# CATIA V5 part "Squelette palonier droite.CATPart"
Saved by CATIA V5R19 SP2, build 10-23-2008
Part number: Squelette palonier droite
Bounding box of the stored display mesh (mm): x 596.282 to 630.035, y -207.652 to -182.406, z 40.783 to 59.385
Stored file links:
  D:\Mes Documents\ressource\CATIA\Ensemble Catia\Voiture_Telecommmande\SchemaCinematiqueFinal\Squelette palonier droite.CATPart
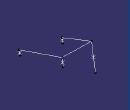
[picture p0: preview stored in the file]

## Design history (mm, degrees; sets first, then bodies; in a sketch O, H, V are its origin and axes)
AxisSystem1: origin (0, 0, 0), X (1, 0, 0), Y (0, 1, 0), Z (0, 0, 1)
Body1 (main body)
  Line1 to Line7: stored without definition
  Point1 to Point4: stored without definition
